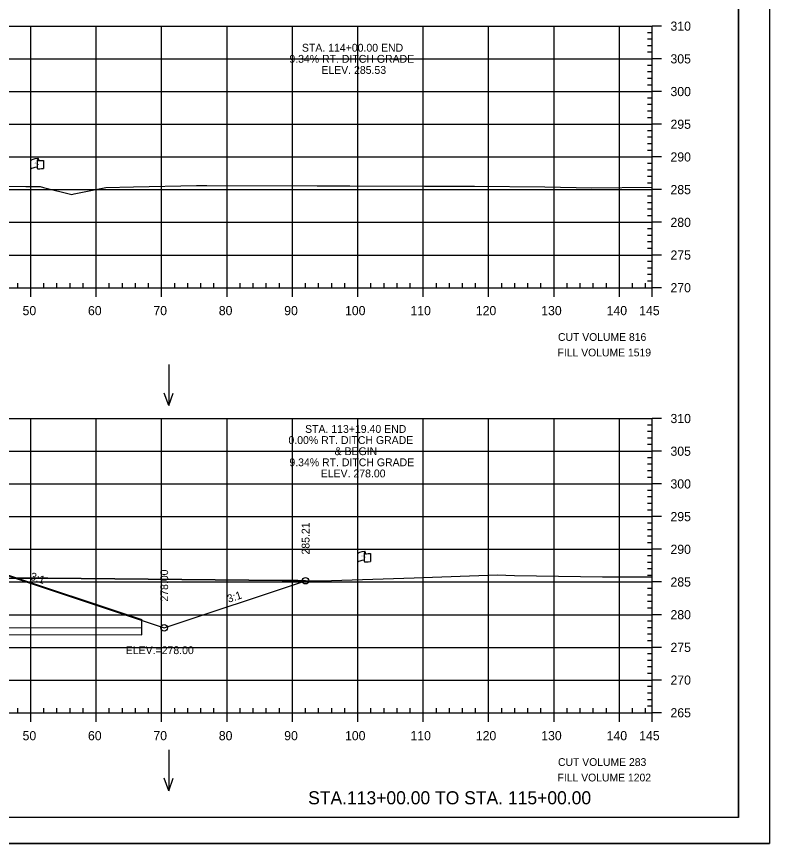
# Model space of a CAD drawing. Extents: x 1370843 to 1371177, y 380307 to 382654.
# Drawn here: x 1371061.5 to 1371176.6, y 381374.2 to 381500.6 of the extents above; entities that cross this region are included whole.
import ezdxf

# ---------------------------------------------------------------- set-up
doc = ezdxf.new("R2010")
doc.units = 0
for name, color, linetype in [('R_Axis', 7, 'Continuous'), ('R_Axis Annot', 7, 'Continuous'), ('R_Border', 7, 'Continuous'), ('R_Border Notes', 7, 'Continuous'), ('R_Draft', 7, 'Continuous'), ('R_Exist Surface', 7, 'Continuous'), ('R_Fin Surface', 7, 'Continuous'), ('R_Fin Surface Annot', 7, 'Continuous'), ('R_Grid', 7, 'Continuous'), ('R_No Plot', 7, 'Continuous'), ('R_ROW', 7, 'Continuous'), ('R_Water', 7, 'Continuous'), ('R_Water Annot', 7, 'Continuous')]:
    doc.layers.add(name, color=color, linetype=linetype)

msp = doc.modelspace()

# ---------------------------------------------------------------- linework, layer by layer
at = {"layer": 'R_Axis'}
for p, q in [((1371158.71, 381459.14), (1371158.71, 381499.14)), ((1371160.11, 381499.14), (1371158.71, 381499.14)), ((1371158.71, 381498.14), (1371158.01, 381498.14)), ((1371158.71, 381497.14), (1371158.01, 381497.14)), ((1371158.71, 381496.14), (1371158.01, 381496.14)), ((1371158.71, 381495.14), (1371158.01, 381495.14)), ((1371160.11, 381494.14), (1371158.71, 381494.14)), ((1371158.71, 381493.14), (1371158.01, 381493.14)), ((1371158.71, 381492.14), (1371158.01, 381492.14)), ((1371158.71, 381491.14), (1371158.01, 381491.14)), ((1371158.71, 381490.14), (1371158.01, 381490.14)), ((1371160.11, 381489.14), (1371158.71, 381489.14)), ((1371158.71, 381488.14), (1371158.01, 381488.14)), ((1371158.71, 381487.14), (1371158.01, 381487.14)), ((1371158.71, 381486.14), (1371158.01, 381486.14)), ((1371158.71, 381485.14), (1371158.01, 381485.14)), ((1371160.11, 381484.14), (1371158.71, 381484.14)), ((1371158.71, 381483.14), (1371158.01, 381483.14)), ((1371158.71, 381482.14), (1371158.01, 381482.14)), ((1371158.71, 381481.14), (1371158.01, 381481.14)), ((1371158.71, 381480.14), (1371158.01, 381480.14)), ((1371160.11, 381479.14), (1371158.71, 381479.14)), ((1371158.71, 381478.14), (1371158.01, 381478.14)), ((1371158.71, 381477.14), (1371158.01, 381477.14)), ((1371158.71, 381476.14), (1371158.01, 381476.14)), ((1371158.71, 381475.14), (1371158.01, 381475.14)), ((1371160.11, 381474.14), (1371158.71, 381474.14)), ((1371158.71, 381473.14), (1371158.01, 381473.14)), ((1371158.71, 381472.14), (1371158.01, 381472.14)), ((1371158.71, 381471.14), (1371158.01, 381471.14)), ((1371158.71, 381470.14), (1371158.01, 381470.14)), ((1371160.11, 381469.14), (1371158.71, 381469.14)), ((1371158.71, 381468.14), (1371158.01, 381468.14)), ((1371158.71, 381467.14), (1371158.01, 381467.14)), ((1371158.71, 381466.14), (1371158.01, 381466.14)), ((1371158.71, 381465.14), (1371158.01, 381465.14)), ((1371160.11, 381464.14), (1371158.71, 381464.14)), ((1371158.71, 381463.14), (1371158.01, 381463.14)), ((1371158.71, 381462.14), (1371158.01, 381462.14)), ((1371158.71, 381461.14), (1371158.01, 381461.14)), ((1371158.71, 381460.14), (1371158.01, 381460.14)), ((1370868.71, 381459.14), (1371158.71, 381459.14)), ((1371061.71, 381459.14), (1371061.71, 381459.84)), ((1371063.71, 381457.74), (1371063.71, 381459.14)), ((1371065.71, 381459.14), (1371065.71, 381459.84)), ((1371067.71, 381459.14), (1371067.71, 381459.84)), ((1371069.71, 381459.14), (1371069.71, 381459.84)), ((1371071.71, 381459.14), (1371071.71, 381459.84)), ((1371073.71, 381457.74), (1371073.71, 381459.14)), ((1371075.71, 381459.14), (1371075.71, 381459.84)), ((1371077.71, 381459.14), (1371077.71, 381459.84)), ((1371079.71, 381459.14), (1371079.71, 381459.84)), ((1371081.71, 381459.14), (1371081.71, 381459.84)), ((1371083.71, 381457.74), (1371083.71, 381459.14)), ((1371085.71, 381459.14), (1371085.71, 381459.84)), ((1371087.71, 381459.14), (1371087.71, 381459.84)), ((1371089.71, 381459.14), (1371089.71, 381459.84)), ((1371091.71, 381459.14), (1371091.71, 381459.84)), ((1371093.71, 381457.74), (1371093.71, 381459.14)), ((1371095.71, 381459.14), (1371095.71, 381459.84)), ((1371097.71, 381459.14), (1371097.71, 381459.84)), ((1371099.71, 381459.14), (1371099.71, 381459.84)), ((1371101.71, 381459.14), (1371101.71, 381459.84)), ((1371103.71, 381457.74), (1371103.71, 381459.14)), ((1371105.71, 381459.14), (1371105.71, 381459.84)), ((1371107.71, 381459.14), (1371107.71, 381459.84)), ((1371109.71, 381459.14), (1371109.71, 381459.84)), ((1371111.71, 381459.14), (1371111.71, 381459.84)), ((1371113.71, 381457.74), (1371113.71, 381459.14)), ((1371115.71, 381459.14), (1371115.71, 381459.84)), ((1371117.71, 381459.14), (1371117.71, 381459.84)), ((1371119.71, 381459.14), (1371119.71, 381459.84)), ((1371121.71, 381459.14), (1371121.71, 381459.84)), ((1371123.71, 381457.74), (1371123.71, 381459.14)), ((1371125.71, 381459.14), (1371125.71, 381459.84)), ((1371127.71, 381459.14), (1371127.71, 381459.84)), ((1371129.71, 381459.14), (1371129.71, 381459.84)), ((1371131.71, 381459.14), (1371131.71, 381459.84)), ((1371133.71, 381457.74), (1371133.71, 381459.14)), ((1371135.71, 381459.14), (1371135.71, 381459.84)), ((1371137.71, 381459.14), (1371137.71, 381459.84)), ((1371139.71, 381459.14), (1371139.71, 381459.84)), ((1371141.71, 381459.14), (1371141.71, 381459.84)), ((1371143.71, 381457.74), (1371143.71, 381459.14)), ((1371145.71, 381459.14), (1371145.71, 381459.84)), ((1371147.71, 381459.14), (1371147.71, 381459.84)), ((1371149.71, 381459.14), (1371149.71, 381459.84)), ((1371151.71, 381459.14), (1371151.71, 381459.84)), ((1371153.71, 381457.74), (1371153.71, 381459.14)), ((1371155.71, 381459.14), (1371155.71, 381459.84)), ((1371157.71, 381459.14), (1371157.71, 381459.84)), ((1371158.71, 381457.74), (1371158.71, 381459.14)), ((1371160.11, 381459.14), (1371158.71, 381459.14)), ((1371158.71, 381394.14), (1371158.71, 381439.14)), ((1371160.11, 381439.14), (1371158.71, 381439.14)), ((1371158.71, 381438.14), (1371158.01, 381438.14)), ((1371158.71, 381437.14), (1371158.01, 381437.14)), ((1371158.71, 381436.14), (1371158.01, 381436.14)), ((1371158.71, 381435.14), (1371158.01, 381435.14)), ((1371160.11, 381434.14), (1371158.71, 381434.14)), ((1371158.71, 381433.14), (1371158.01, 381433.14)), ((1371158.71, 381432.14), (1371158.01, 381432.14)), ((1371158.71, 381431.14), (1371158.01, 381431.14)), ((1371158.71, 381430.14), (1371158.01, 381430.14)), ((1371160.11, 381429.14), (1371158.71, 381429.14)), ((1371158.71, 381428.14), (1371158.01, 381428.14)), ((1371158.71, 381427.14), (1371158.01, 381427.14)), ((1371158.71, 381426.14), (1371158.01, 381426.14)), ((1371158.71, 381425.14), (1371158.01, 381425.14)), ((1371160.11, 381424.14), (1371158.71, 381424.14)), ((1371158.71, 381423.14), (1371158.01, 381423.14)), ((1371158.71, 381422.14), (1371158.01, 381422.14)), ((1371158.71, 381421.14), (1371158.01, 381421.14)), ((1371158.71, 381420.14), (1371158.01, 381420.14)), ((1371160.11, 381419.14), (1371158.71, 381419.14)), ((1371158.71, 381418.14), (1371158.01, 381418.14)), ((1371158.71, 381417.14), (1371158.01, 381417.14)), ((1371158.71, 381416.14), (1371158.01, 381416.14)), ((1371158.71, 381415.14), (1371158.01, 381415.14)), ((1371158.71, 381413.14), (1371158.01, 381413.14)), ((1371160.11, 381414.14), (1371158.71, 381414.14)), ((1371158.71, 381412.14), (1371158.01, 381412.14)), ((1371158.71, 381411.14), (1371158.01, 381411.14)), ((1371158.71, 381410.14), (1371158.01, 381410.14)), ((1371158.71, 381408.14), (1371158.01, 381408.14)), ((1371160.11, 381409.14), (1371158.71, 381409.14)), ((1371158.71, 381407.14), (1371158.01, 381407.14)), ((1371158.71, 381406.14), (1371158.01, 381406.14)), ((1371158.71, 381405.14), (1371158.01, 381405.14)), ((1371158.71, 381403.14), (1371158.01, 381403.14)), ((1371160.11, 381404.14), (1371158.71, 381404.14)), ((1371158.71, 381402.14), (1371158.01, 381402.14)), ((1371158.71, 381401.14), (1371158.01, 381401.14)), ((1371158.71, 381400.14), (1371158.01, 381400.14)), ((1371158.71, 381398.14), (1371158.01, 381398.14)), ((1371160.11, 381399.14), (1371158.71, 381399.14)), ((1371158.71, 381397.14), (1371158.01, 381397.14)), ((1371158.71, 381396.14), (1371158.01, 381396.14)), ((1370868.71, 381394.14), (1371158.71, 381394.14)), ((1371061.71, 381394.14), (1371061.71, 381394.84)), ((1371063.71, 381392.74), (1371063.71, 381394.14)), ((1371065.71, 381394.14), (1371065.71, 381394.84)), ((1371067.71, 381394.14), (1371067.71, 381394.84)), ((1371069.71, 381394.14), (1371069.71, 381394.84)), ((1371071.71, 381394.14), (1371071.71, 381394.84)), ((1371073.71, 381392.74), (1371073.71, 381394.14)), ((1371075.71, 381394.14), (1371075.71, 381394.84)), ((1371077.71, 381394.14), (1371077.71, 381394.84)), ((1371079.71, 381394.14), (1371079.71, 381394.84)), ((1371081.71, 381394.14), (1371081.71, 381394.84)), ((1371083.71, 381392.74), (1371083.71, 381394.14)), ((1371085.71, 381394.14), (1371085.71, 381394.84)), ((1371087.71, 381394.14), (1371087.71, 381394.84)), ((1371089.71, 381394.14), (1371089.71, 381394.84)), ((1371091.71, 381394.14), (1371091.71, 381394.84)), ((1371093.71, 381392.74), (1371093.71, 381394.14)), ((1371095.71, 381394.14), (1371095.71, 381394.84)), ((1371097.71, 381394.14), (1371097.71, 381394.84)), ((1371099.71, 381394.14), (1371099.71, 381394.84)), ((1371101.71, 381394.14), (1371101.71, 381394.84)), ((1371103.71, 381392.74), (1371103.71, 381394.14)), ((1371105.71, 381394.14), (1371105.71, 381394.84)), ((1371107.71, 381394.14), (1371107.71, 381394.84)), ((1371109.71, 381394.14), (1371109.71, 381394.84)), ((1371111.71, 381394.14), (1371111.71, 381394.84)), ((1371113.71, 381392.74), (1371113.71, 381394.14)), ((1371115.71, 381394.14), (1371115.71, 381394.84)), ((1371117.71, 381394.14), (1371117.71, 381394.84)), ((1371119.71, 381394.14), (1371119.71, 381394.84)), ((1371121.71, 381394.14), (1371121.71, 381394.84)), ((1371123.71, 381392.74), (1371123.71, 381394.14)), ((1371125.71, 381394.14), (1371125.71, 381394.84)), ((1371127.71, 381394.14), (1371127.71, 381394.84)), ((1371129.71, 381394.14), (1371129.71, 381394.84)), ((1371131.71, 381394.14), (1371131.71, 381394.84)), ((1371133.71, 381392.74), (1371133.71, 381394.14)), ((1371135.71, 381394.14), (1371135.71, 381394.84)), ((1371137.71, 381394.14), (1371137.71, 381394.84)), ((1371139.71, 381394.14), (1371139.71, 381394.84)), ((1371141.71, 381394.14), (1371141.71, 381394.84)), ((1371143.71, 381392.74), (1371143.71, 381394.14)), ((1371145.71, 381394.14), (1371145.71, 381394.84)), ((1371147.71, 381394.14), (1371147.71, 381394.84)), ((1371149.71, 381394.14), (1371149.71, 381394.84)), ((1371151.71, 381394.14), (1371151.71, 381394.84)), ((1371153.71, 381392.74), (1371153.71, 381394.14)), ((1371155.71, 381394.14), (1371155.71, 381394.84)), ((1371157.71, 381394.14), (1371157.71, 381394.84)), ((1371158.71, 381395.14), (1371158.01, 381395.14)), ((1371158.71, 381392.74), (1371158.71, 381394.14)), ((1371160.11, 381394.14), (1371158.71, 381394.14))]:
    msp.add_line(p, q, dxfattribs=at)
at = {"layer": 'R_Border'}
for q in [(1371171.89, 381583.6), (1370855.71, 381378.14)]:
    msp.add_line((1371171.89, 381378.14), q, dxfattribs=at)
at = {"layer": 'R_Exist Surface'}
for points in [[(1371049.05, 381474.7), (1371062.93, 381474.6), (1371065.16, 381474.61), (1371065.64, 381474.48), (1371069.96, 381473.41), (1371070.32, 381473.5), (1371075.16, 381474.48), (1371079.42, 381474.58), (1371089.05, 381474.78), (1371090.62, 381474.77), (1371107.48, 381474.74), (1371112.5, 381474.71), (1371123.92, 381474.68), (1371131.54, 381474.65), (1371142.29, 381474.59), (1371149.48, 381474.44), (1371158.71, 381474.53)], [(1371059.55, 381414.72), (1371066.32, 381414.73), (1371102.12, 381414.36), (1371104.53, 381414.35), (1371105.46, 381414.35), (1371108.11, 381414.32), (1371122.34, 381414.8), (1371135.02, 381415.21), (1371137.67, 381415.14), (1371151.09, 381414.94), (1371158.71, 381414.92)]]:
    msp.add_lwpolyline(points, dxfattribs=at)
at = {"layer": 'R_Fin Surface'}
msp.add_lwpolyline([(1370923.59, 381413.79), (1370942.96, 381407.34), (1370982.71, 381420.59), (1370983.71, 381420.59), (1370990.11, 381421.35), (1371000.71, 381422.6), (1371002.71, 381422.68), (1371013.71, 381422.9), (1371024.71, 381422.68), (1371026.71, 381422.6), (1371036.65, 381421.36), (1371042.71, 381420.6), (1371043.21, 381420.43), (1371044.21, 381420.43), (1371084.1, 381407.14), (1371105.72, 381414.34)], dxfattribs=at)
at = {"layer": 'R_Grid'}
for p, q in [((1370868.71, 381499.14), (1371158.71, 381499.14)), ((1371063.71, 381459.14), (1371063.71, 381499.14)), ((1371073.71, 381459.14), (1371073.71, 381499.14)), ((1371083.71, 381459.14), (1371083.71, 381499.14)), ((1371093.71, 381459.14), (1371093.71, 381499.14)), ((1371103.71, 381459.14), (1371103.71, 381499.14)), ((1371113.71, 381459.14), (1371113.71, 381499.14)), ((1371123.71, 381459.14), (1371123.71, 381499.14)), ((1371133.71, 381459.14), (1371133.71, 381499.14)), ((1371143.71, 381459.14), (1371143.71, 381499.14)), ((1371153.71, 381459.14), (1371153.71, 381499.14)), ((1371158.71, 381459.14), (1371158.71, 381499.14)), ((1370868.71, 381494.14), (1371158.71, 381494.14)), ((1370868.71, 381489.14), (1371158.71, 381489.14)), ((1370868.71, 381484.14), (1371158.71, 381484.14)), ((1370868.71, 381479.14), (1371158.71, 381479.14)), ((1370868.71, 381474.14), (1371158.71, 381474.14)), ((1370868.71, 381469.14), (1371158.71, 381469.14)), ((1370868.71, 381464.14), (1371158.71, 381464.14)), ((1370868.71, 381459.14), (1371158.71, 381459.14)), ((1370868.71, 381439.14), (1371158.71, 381439.14)), ((1371063.71, 381394.14), (1371063.71, 381439.14)), ((1371073.71, 381394.14), (1371073.71, 381439.14)), ((1371083.71, 381394.14), (1371083.71, 381439.14)), ((1371093.71, 381394.14), (1371093.71, 381439.14)), ((1371103.71, 381394.14), (1371103.71, 381439.14)), ((1371113.71, 381394.14), (1371113.71, 381439.14)), ((1371123.71, 381394.14), (1371123.71, 381439.14)), ((1371133.71, 381394.14), (1371133.71, 381439.14)), ((1371143.71, 381394.14), (1371143.71, 381439.14)), ((1371153.71, 381394.14), (1371153.71, 381439.14)), ((1371158.71, 381394.14), (1371158.71, 381439.14)), ((1370868.71, 381434.14), (1371158.71, 381434.14)), ((1370868.71, 381429.14), (1371158.71, 381429.14)), ((1370868.71, 381424.14), (1371158.71, 381424.14)), ((1370868.71, 381419.14), (1371158.71, 381419.14)), ((1370868.71, 381414.14), (1371158.71, 381414.14)), ((1370868.71, 381409.14), (1371158.71, 381409.14)), ((1370868.71, 381404.14), (1371158.71, 381404.14)), ((1370868.71, 381399.14), (1371158.71, 381399.14)), ((1370868.71, 381394.14), (1371158.71, 381394.14))]:
    msp.add_line(p, q, dxfattribs=at)
at = {"layer": 'R_No Plot'}
msp.add_line((1370843.31, 381374.16), (1371176.64, 381374.16), dxfattribs=at)
for points in [[(1370843.3, 381587.49), (1371176.64, 381587.49), (1371176.64, 381374.16), (1370843.3, 381374.16)], [(1371089.63, 381583.6), (1371089.63, 381573.72), (1371125.36, 381573.72), (1371125.36, 381570.8), (1371148.56, 381570.8), (1371148.56, 381546.47), (1371171.89, 381546.47), (1371171.89, 381378.14), (1370855.71, 381378.14), (1370855.71, 381583.6)], [(1371066.32, 381414.73), (1371061.34, 381414.72), (1371084.1, 381407.14), (1371105.72, 381414.34), (1371104.53, 381414.35), (1371102.12, 381414.36)]]:
    msp.add_lwpolyline(points, close=True, dxfattribs=at)
for centre in [(1371105.72, 381414.34), (1371084.1, 381407.14)]:
    msp.add_circle(centre, 0.5, dxfattribs=at)
at = {"layer": 'R_ROW'}
for p, q in [((1371063.71, 381474.61), (1371063.71, 381478.56)), ((1371064.7, 381478.65), (1371064.7, 381478.64)), ((1371064.7, 381478.64), (1371064.7, 381477.41)), ((1371064.87, 381478.81), (1371064.87, 381478.57)), ((1371065.64, 381478.61), (1371065.64, 381477.37)), ((1371113.69, 381414.5), (1371113.69, 381418.46)), ((1371114.68, 381418.55), (1371114.68, 381418.54)), ((1371114.68, 381418.54), (1371114.68, 381417.31)), ((1371114.85, 381418.71), (1371114.85, 381418.47)), ((1371115.62, 381418.51), (1371115.62, 381417.27))]:
    msp.add_line(p, q, dxfattribs=at)
for centre, radius, start, end in [((1371064.79, 381478.81), 0.0783, 263.0712, 93.9564), ((1371064.78, 381478.65), 0.078, 88.6458, 274.2828), ((1371064.78, 381477.41), 0.0783, 180, 273.9564), ((1371114.76, 381418.55), 0.078, 88.6458, 274.2828), ((1371114.77, 381418.71), 0.0783, 263.0712, 93.9564), ((1371114.76, 381417.31), 0.0783, 180, 273.9564)]:
    msp.add_arc(centre, radius, start, end, dxfattribs=at)
for centre, major_axis, ratio, start_param, end_param in [((1371065.29, 381478.6), (-1.58, -0.04), 0.19887, 5.030368, 6.283185), ((1371066, 381478.72), (-1.23, -0.13), 0.052933, 0.159456, 1.268315), ((1371065.29, 381477.28), (-1.58, -0.04), 0.19887, 5.083035, 6.194897), ((1371066, 381477.48), (-1.23, -0.13), 0.052933, 0.159456, 1.268315), ((1371115.27, 381418.5), (-1.58, -0.04), 0.19887, 5.030368, 6.283185), ((1371115.98, 381418.61), (-1.23, -0.13), 0.052933, 0.159456, 1.268315), ((1371115.27, 381417.18), (-1.58, -0.04), 0.19887, 5.083035, 6.194897), ((1371115.98, 381417.37), (-1.23, -0.13), 0.052933, 0.159456, 1.268315)]:
    msp.add_ellipse(centre, major_axis=major_axis, ratio=ratio, start_param=start_param, end_param=end_param, dxfattribs=at)
at = {"layer": 'R_Water'}
for p, q in [((1371044.66, 381420.39), (1371080.66, 381408.39)), ((1370946.72, 381407.34), (1371080.66, 381407.14)), ((1370946.72, 381406.47), (1371080.66, 381406.04))]:
    msp.add_line(p, q, dxfattribs=at)
msp.add_lwpolyline([(1371080.66, 381406.04), (1371080.66, 381406.04), (1371080.66, 381408.39)], dxfattribs=at)
at = {"layer": 'R_Water Annot'}
for p, q in [((1371084.79, 381447.41), (1371084.79, 381441.12)), ((1371084.79, 381441.12), (1371084.09, 381443.04)), ((1371084.79, 381441.12), (1371085.49, 381443.04)), ((1371084.79, 381388.48), (1371084.79, 381382.2)), ((1371084.79, 381382.2), (1371084.09, 381384.12)), ((1371084.79, 381382.2), (1371085.49, 381384.12))]:
    msp.add_line(p, q, dxfattribs=at)

# ---------------------------------------------------------------- texts
at = {"layer": 'R_Axis Annot'}
for s, p in [('310', (1371161.51, 381498.44)), ('305', (1371161.51, 381493.44)), ('300', (1371161.51, 381488.44)), ('295', (1371161.51, 381483.44)), ('290', (1371161.51, 381478.44)), ('285', (1371161.51, 381473.44)), ('280', (1371161.51, 381468.44)), ('275', (1371161.51, 381463.44)), ('270', (1371161.51, 381458.44)), ('50', (1371062.45, 381454.94)), ('60', (1371072.45, 381454.94)), ('70', (1371082.45, 381454.94)), ('80', (1371092.45, 381454.94)), ('90', (1371102.45, 381454.94)), ('100', (1371111.75, 381454.94)), ('110', (1371121.75, 381454.94)), ('120', (1371131.75, 381454.94)), ('130', (1371141.75, 381454.94)), ('140', (1371151.75, 381454.94)), ('145', (1371156.73, 381454.94)), ('310', (1371161.51, 381438.44)), ('305', (1371161.51, 381433.44)), ('300', (1371161.51, 381428.44)), ('295', (1371161.51, 381423.44)), ('290', (1371161.51, 381418.44)), ('285', (1371161.51, 381413.44)), ('280', (1371161.51, 381408.44)), ('275', (1371161.51, 381403.44)), ('270', (1371161.51, 381398.44)), ('265', (1371161.51, 381393.44)), ('50', (1371062.45, 381389.94)), ('60', (1371072.45, 381389.94)), ('70', (1371082.45, 381389.94)), ('80', (1371092.45, 381389.94)), ('90', (1371102.45, 381389.94)), ('100', (1371111.75, 381389.94)), ('110', (1371121.75, 381389.94)), ('120', (1371131.75, 381389.94)), ('130', (1371141.75, 381389.94)), ('140', (1371151.75, 381389.94)), ('145', (1371156.73, 381389.94))]:
    msp.add_text(s, height=1.4, dxfattribs=at).set_placement(p)
at = {"layer": 'R_Border Notes'}
for s, p in [('CUT VOLUME 816', (1371144.31, 381451.01)), ('FILL VOLUME 1519', (1371144.24, 381448.64)), ('CUT VOLUME 283', (1371144.31, 381386.01)), ('FILL VOLUME 1202', (1371144.24, 381383.64))]:
    msp.add_text(s, height=1.1875, dxfattribs=at).set_placement(p)
at = {"layer": 'R_Draft'}
msp.add_text('STA.113+00.00 TO STA. 115+00.00', height=2, dxfattribs=at).set_placement((1371106.11, 381380.14))
at = {"layer": 'R_Fin Surface Annot'}
for s, rotation, p in [('285.21', 90, (1371106.32, 381418.34)), ('278.00', 90, (1371084.7, 381411.14)), ('3:1', 341.5651, (1371063.52, 381414.52)), ('3:1', 18.4349, (1371093.96, 381410.95))]:
    msp.add_text(s, height=1.2, rotation=rotation, dxfattribs=at).set_placement(p)
at = {"layer": 'R_ROW'}
for s, height, rotation, p in [('R ', 0.2, 9.9884, (1371064.23, 381478.06)), (' O', 0.2, 9.9884, (1371064.37, 381478.1)), ('W', 0.2, 351.1788, (1371064.7, 381477.94)), ('DWB 11-9-07', 0.001, 90, (1371064.87, 381478.57)), ('DWB 11-9-07', 0.001, 5.0717, (1371065.63, 381477.37)), ('DWB 11-9-07', 0.001, 90, (1371063.71, 381474.61)), ('R ', 0.2, 9.9884, (1371114.21, 381417.96)), (' O', 0.2, 9.9884, (1371114.35, 381418)), ('DWB 11-9-07', 0.001, 90, (1371114.85, 381418.47)), ('W', 0.2, 351.1788, (1371114.68, 381417.83)), ('DWB 11-9-07', 0.001, 5.0717, (1371115.61, 381417.27)), ('DWB 11-9-07', 0.001, 90, (1371113.69, 381414.51))]:
    msp.add_text(s, height=height, rotation=rotation, dxfattribs=at).set_placement(p)
at = {"layer": 'R_Water Annot'}
for s, p in [('STA. 114+00.00 END', (1371105.16, 381495.24)), ('9.34% RT. DITCH GRADE', (1371103.24, 381493.54)), ('ELEV. 285.53', (1371108.13, 381491.84)), ('STA. 113+19.40 END', (1371105.64, 381436.94)), ('0.00% RT. DITCH GRADE', (1371103.1, 381435.24)), ('& BEGIN', (1371110.16, 381433.54)), ('9.34% RT. DITCH GRADE', (1371103.24, 381431.84)), ('ELEV. 278.00', (1371108.04, 381430.14)), ('ELEV.=278.00', (1371078.23, 381403.11))]:
    msp.add_text(s, height=1.2, dxfattribs=at).set_placement(p)

doc.saveas('drawing.dxf')
